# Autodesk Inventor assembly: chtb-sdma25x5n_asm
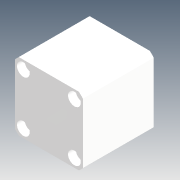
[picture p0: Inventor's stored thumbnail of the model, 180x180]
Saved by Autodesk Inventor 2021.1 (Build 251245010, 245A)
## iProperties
Company: Microsoft
Created: 2018-05
Part Number: chtb-sdma25x5n_asm
Description: STEP AP214
Document SubType Name: Assembly
Designer: user
Title: chtb-sdma25x5n_asm.STEP
Author: Windows
Revision Number: ÈÎºÎ
Sending System: SolidWorks 2015
Preprocessor: SwSTEP 2.0
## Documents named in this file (4)
- D:\Vault_2016\Projekty\Clamptek\Hydraulic\CHTB\CHTB-25\Inventor\chtb-sdma25x5n\chtb-sdma25x5n_asm.iam
- D:\Vault_2016\Projekty\Clamptek\Hydraulic\CHTB\CHTB-25\Inventor\chtb-sdma25x5n\CHTB-25QG.ipt
- D:\Vault_2016\Projekty\Clamptek\Hydraulic\CHTB\CHTB-25\Inventor\chtb-sdma25x5n\CHTB-SDMA25X5NBT.ipt
- D:\Vault_2016\Projekty\Clamptek\Hydraulic\CHTB\CHTB-25\Inventor\chtb-sdma25x5n\CHTB-SDMA25X5NHSG.ipt
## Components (3 placed, 3 different names)
1. CHTB-25QG_1
2. CHTB-SDMA25X5NBT_2
3. CHTB-SDMA25X5NHSG_3
